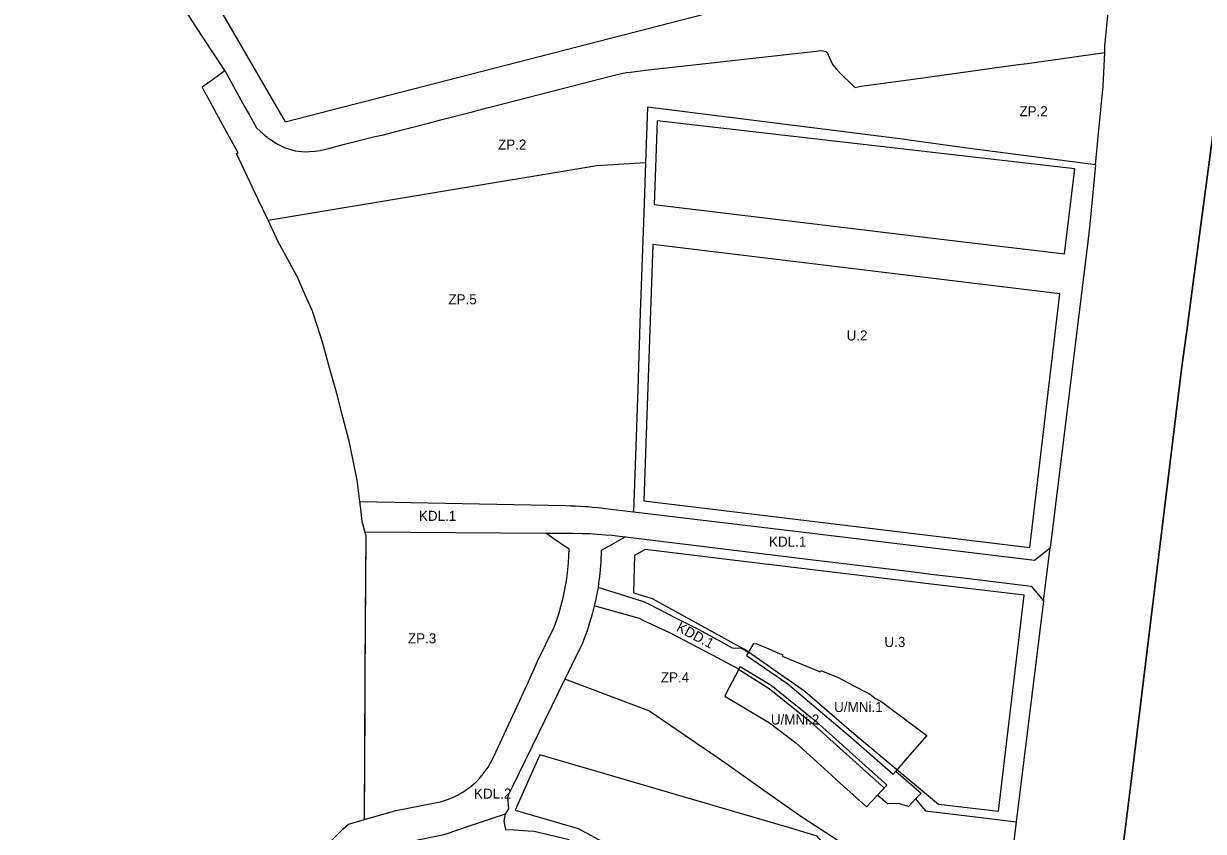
# Model space of a CAD drawing. Extents: x 7427578 to 7429232, y 5547102 to 5548448.
# Drawn here: x 7428072 to 7428660, y 5547522 to 5547924 of the extents above; entities that cross this region are included whole.
import ezdxf

# ---------------------------------------------------------------- set-up
doc = ezdxf.new("R2010")
doc.units = 0
for name, color, linetype in [('LIN_Granica Planu', 7, 'Continuous'), ('LIN_Linia Zabudowy Nieprzekraczalna', 7, 'Continuous'), ('LIN_Linie Rozgraniczajace', 7, 'Continuous'), ('TXT_Oznaczenia Przeznaczenia', 7, 'Continuous')]:
    doc.layers.add(name, color=color, linetype=linetype)

msp = doc.modelspace()

# ---------------------------------------------------------------- linework, layer by layer
at = {"layer": 'LIN_Granica Planu'}
for points in [[(7428228.98, 5547520.95), (7428231.59, 5547523.32), (7428234.21, 5547525.69), (7428242.1, 5547527.99), (7428242.5, 5547598.62), (7428242.91, 5547669.26), (7428241.96, 5547672.78), (7428241.02, 5547676.3), (7428240.42, 5547681.38), (7428239.81, 5547686.46), (7428239.15, 5547691.75), (7428238.48, 5547697.04), (7428236.46, 5547706.78), (7428234.44, 5547716.52), (7428231.38, 5547728.4), (7428228.32, 5547740.27), (7428224.76, 5547753.07), (7428221.2, 5547765.86), (7428218.73, 5547773.5), (7428216.25, 5547781.15), (7428212.48, 5547789.66), (7428208.71, 5547798.17), (7428203.95, 5547806.94), (7428199.18, 5547815.71), (7428194.13, 5547826.46), (7428189.08, 5547837.21), (7428183.79, 5547848.51), (7428178.49, 5547859.81), (7428178.83, 5547859.98), (7428179.17, 5547860.14), (7428171.64, 5547873.88), (7428164.11, 5547887.63), (7428162.68, 5547890.25), (7428161.25, 5547892.87), (7428166.91, 5547896.97), (7428172.56, 5547901.07), (7428161.38, 5547918.19), (7428150.21, 5547935.3)], [(7428665.68, 5547877.89), (7428654.7, 5547795.42), (7428651.83, 5547773.84), (7428648.96, 5547752.25), (7428639.46, 5547674.85), (7428629.96, 5547597.45), (7428623.59, 5547545.62), (7428617.23, 5547493.78)]]:
    msp.add_lwpolyline(points, dxfattribs=at)
at = {"layer": 'LIN_Linia Zabudowy Nieprzekraczalna'}
msp.add_line((7428381.21, 5547686.74), (7428573.36, 5547663.57), dxfattribs=at)
for points in [[(7428142.27, 5548072), (7428125.7, 5548050.16), (7428145.32, 5547974.26), (7428202.61, 5547875.54), (7428509.21, 5547954.46), (7428604.85, 5547945.18), (7428623.63, 5548139.34), (7428464.48, 5548154.75), (7428464.48, 5548154.75)], [(7428387.79, 5547876.03), (7428386.34, 5547834.42), (7428532.04, 5547816.82), (7428590.73, 5547809.73), (7428595.77, 5547852.08)], [(7428432.15, 5547612.46), (7428432.22, 5547612.4), (7428461.39, 5547591.9), (7428485.79, 5547570.81), (7428527.92, 5547535.6), (7428557.73, 5547532.13), (7428570.52, 5547639.72), (7428522.86, 5547645.41), (7428480.39, 5547650.58), (7428430.78, 5547656.57), (7428395.48, 5547660.82), (7428381.88, 5547662.54), (7428376.52, 5547659.54), (7428376.12, 5547640.92), (7428385.32, 5547638.06), (7428427.92, 5547614.77)], [(7428329.45, 5547560.25), (7428317.14, 5547532.66), (7428348.48, 5547523.48), (7428419.09, 5547485.39), (7428479.17, 5547406.37), (7428527.46, 5547399.74), (7428536, 5547434.01), (7428536, 5547434.01), (7428502.3, 5547478.77), (7428467.47, 5547519.82), (7428467.47, 5547519.82), (7428454.97, 5547523.48)]]:
    msp.add_lwpolyline(points, close=True, dxfattribs=at)
for points in [[(7428588.37, 5547789.87), (7428385.64, 5547814.36), (7428381.21, 5547686.74)], [(7428573.36, 5547663.57), (7428588.37, 5547789.87)], [(7428443.6, 5547593.1), (7428433.79, 5547599.32), (7428428.39, 5547602.75)], [(7428500.81, 5547543.72), (7428500.02, 5547544.55), (7428465.67, 5547575.32), (7428443.6, 5547593.1)]]:
    msp.add_lwpolyline(points, dxfattribs=at)
at = {"layer": 'LIN_Linie Rozgraniczajace'}
msp.add_line((7428580.21, 5547636.88), (7428583.49, 5547663.39), dxfattribs=at)
for points in [[(7428610.65, 5547910.02), (7428610.8, 5547913.24), (7428612.62, 5547931.79), (7428613.59, 5547941.57), (7428614.56, 5547951.51), (7428616.89, 5547975.32), (7428619.5, 5548002.1), (7428621.45, 5548022.13), (7428623.35, 5548041.5), (7428625.12, 5548059.63), (7428626.99, 5548078.82), (7428628.88, 5548098.19), (7428631.03, 5548120.27), (7428633.19, 5548142.37), (7428635.26, 5548163.57), (7428637.68, 5548188.34), (7428639.03, 5548202.16), (7428639.7, 5548209.08), (7428642.48, 5548237.53), (7428644.51, 5548258.34), (7428645.39, 5548267.36), (7428646.37, 5548277.45)], [(7428172.56, 5547901.07), (7428161.38, 5547918.19), (7428150.21, 5547935.3), (7428144.8, 5547942.14), (7428139.39, 5547948.98), (7428130.06, 5547960.77), (7428125.03, 5547967.12), (7428120.61, 5547972.54), (7428114.73, 5547977.58), (7428108.84, 5547982.62), (7428096.04, 5547993.58), (7428086.98, 5548002.36), (7428077.46, 5548010), (7428072.43, 5548014.03)], [(7428172.56, 5547901.07), (7428182.54, 5547882.87), (7428184.65, 5547879.13), (7428188.37, 5547872.52), (7428190.21, 5547870.82), (7428194.08, 5547867.6), (7428198.26, 5547864.8), (7428200.35, 5547863.73), (7428202.73, 5547862.52), (7428207.55, 5547861.13), (7428212.56, 5547860.65), (7428214.84, 5547860.75), (7428217.59, 5547860.86), (7428220.06, 5547861.17), (7428224.92, 5547862.43), (7428232.18, 5547864.31), (7428239.45, 5547866.19), (7428246.71, 5547868.07), (7428251.64, 5547869.06), (7428259.57, 5547871.12), (7428266.82, 5547873.01), (7428274.08, 5547874.9), (7428281.34, 5547876.78), (7428288.6, 5547878.67), (7428295.86, 5547880.56), (7428303.12, 5547882.45), (7428305.24, 5547883), (7428364.63, 5547898.26), (7428367.26, 5547898.87), (7428372.5, 5547900.09), (7428374.61, 5547900.33), (7428382.06, 5547901.17), (7428389.51, 5547902.01), (7428396.96, 5547902.85), (7428404.42, 5547903.7), (7428411.87, 5547904.54), (7428419.32, 5547905.38), (7428426.77, 5547906.22), (7428434.23, 5547907.07), (7428441.68, 5547907.91), (7428449.13, 5547908.75), (7428456.58, 5547909.59), (7428464.04, 5547910.44), (7428468.15, 5547910.9), (7428469.43, 5547910.98), (7428470.55, 5547910.94), (7428471.87, 5547910.51), (7428472.59, 5547909.76), (7428475.03, 5547904.36), (7428475.81, 5547903.24), (7428478.05, 5547900.54), (7428486.28, 5547892.58), (7428489.28, 5547893.24), (7428509.15, 5547895.97), (7428514.11, 5547896.65), (7428567.51, 5547904), (7428572.05, 5547904.62), (7428610.65, 5547910.02)], [(7428606.08, 5547854.17), (7428607.6, 5547869.74), (7428609.89, 5547893.2), (7428610.65, 5547910.02)], [(7428194.13, 5547826.46), (7428189.08, 5547837.21), (7428183.79, 5547848.51), (7428178.49, 5547859.81), (7428178.83, 5547859.98), (7428179.17, 5547860.14), (7428171.64, 5547873.88), (7428164.11, 5547887.63), (7428162.68, 5547890.25), (7428161.25, 5547892.87), (7428166.91, 5547896.97), (7428172.56, 5547901.07)], [(7428606.08, 5547854.17), (7428543.35, 5547862.23), (7428514.55, 5547866.27), (7428509.94, 5547866.95), (7428383.04, 5547882.83), (7428382.09, 5547855.29)], [(7428617.23, 5547493.78), (7428623.59, 5547545.62), (7428629.96, 5547597.45), (7428639.46, 5547674.85), (7428648.96, 5547752.25), (7428651.83, 5547773.84), (7428654.7, 5547795.42), (7428665.68, 5547877.89)], [(7428194.13, 5547826.46), (7428357.87, 5547853.75), (7428382.09, 5547855.29)], [(7428382.09, 5547855.29), (7428381.22, 5547829.81), (7428379.41, 5547780.47), (7428378.74, 5547758.97), (7428378.18, 5547742.3), (7428376.5, 5547695.04), (7428376.01, 5547681.32)], [(7428606.08, 5547854.17), (7428603.19, 5547824.54), (7428602.34, 5547815.75), (7428583.49, 5547663.39)], [(7428239.81, 5547686.46), (7428239.15, 5547691.75), (7428238.48, 5547697.04), (7428236.46, 5547706.78), (7428234.44, 5547716.52), (7428231.38, 5547728.4), (7428228.32, 5547740.27), (7428224.76, 5547753.07), (7428221.2, 5547765.86), (7428218.73, 5547773.5), (7428216.25, 5547781.15), (7428212.48, 5547789.66), (7428208.71, 5547798.17), (7428203.95, 5547806.94), (7428199.18, 5547815.71), (7428194.13, 5547826.46)], [(7428242.38, 5547671.25), (7428241.96, 5547672.78), (7428241.02, 5547676.3), (7428240.42, 5547681.38), (7428239.81, 5547686.46)], [(7428239.81, 5547686.46), (7428342.06, 5547684.41), (7428344.62, 5547684.34), (7428347.21, 5547684.24), (7428349.71, 5547684.11), (7428351.82, 5547683.97), (7428353.38, 5547683.86), (7428355.66, 5547683.67), (7428358.66, 5547683.38), (7428361.99, 5547683.01), (7428376.01, 5547681.32)], [(7428376.01, 5547681.32), (7428466.28, 5547670.43), (7428575.67, 5547657.24), (7428583.49, 5547663.39)], [(7428242.1, 5547527.99), (7428242.41, 5547583.14), (7428242.5, 5547598.62), (7428242.52, 5547601.94), (7428242.68, 5547628.62), (7428242.91, 5547669.26), (7428242.38, 5547671.25)], [(7428242.38, 5547671.25), (7428332.38, 5547670.71)], [(7428242.1, 5547527.99), (7428257.78, 5547532.56), (7428275.73, 5547536.01), (7428280.02, 5547536.91), (7428283.42, 5547537.96), (7428286.47, 5547539.18), (7428288.53, 5547540.18), (7428291.1, 5547541.65), (7428295.07, 5547544.46), (7428297.7, 5547546.77), (7428299.25, 5547548.33), (7428301.29, 5547550.71), (7428303.7, 5547554.07), (7428306.56, 5547559.37), (7428323.42, 5547595.94), (7428324.61, 5547598.6), (7428326.78, 5547603.44), (7428328.33, 5547606.89), (7428336.57, 5547623.85), (7428338.03, 5547628.04), (7428339.02, 5547630.9), (7428341.22, 5547639.2), (7428342.7, 5547646.98), (7428343.23, 5547650.97), (7428343.76, 5547655.94), (7428343.92, 5547659.23), (7428344.08, 5547662.64), (7428338.15, 5547666.73), (7428332.38, 5547670.71)], [(7428332.38, 5547670.71), (7428337.4, 5547670.68), (7428341.76, 5547670.65), (7428346.07, 5547670.63), (7428350.56, 5547670.55), (7428354.4, 5547670.41), (7428357.97, 5547670.21), (7428362.08, 5547669.89), (7428365.42, 5547669.58), (7428367.81, 5547669.32), (7428369.12, 5547669.16), (7428372.13, 5547668.8)], [(7428372.13, 5547668.8), (7428365.1, 5547664.86), (7428360.04, 5547662.04), (7428359.81, 5547656.5), (7428359.49, 5547652.39), (7428359.14, 5547648.92), (7428358.72, 5547645.88), (7428358.4, 5547643.56)], [(7428372.13, 5547668.8), (7428464.2, 5547657.59), (7428490.63, 5547654.37), (7428517.06, 5547651.15), (7428524.16, 5547650.29), (7428528.62, 5547649.75), (7428540.44, 5547648.34), (7428574.07, 5547644.32), (7428580.21, 5547636.88)], [(7428358.4, 5547643.56), (7428357.68, 5547639.53), (7428357.11, 5547636.91), (7428356.57, 5547634.44)], [(7428433.26, 5547611.15), (7428429.83, 5547613.27), (7428425.42, 5547613.42), (7428418.29, 5547617.35), (7428408.11, 5547622.88), (7428397.87, 5547628.04), (7428383.98, 5547635.06), (7428381.22, 5547636.46), (7428358.4, 5547643.56)], [(7428580.21, 5547636.88), (7428566.6, 5547526.89)], [(7428356.57, 5547634.44), (7428355.52, 5547630.32), (7428354.08, 5547625.44), (7428352.93, 5547621.98), (7428351.84, 5547618.99), (7428350.29, 5547615.06), (7428347.91, 5547610.21), (7428345.25, 5547604.75), (7428343.36, 5547600.9), (7428341.88, 5547597.87)], [(7428428.52, 5547602.99), (7428415.14, 5547609.99), (7428394.44, 5547620.83), (7428380.9, 5547627.21), (7428379.02, 5547628.1), (7428356.57, 5547634.44)], [(7428433.26, 5547611.15), (7428435.97, 5547615.69), (7428437.41, 5547615.49), (7428442.25, 5547613.47), (7428447.93, 5547611.1), (7428450.38, 5547610.08), (7428450.09, 5547609.39), (7428460.18, 5547605.19), (7428469.06, 5547601.62), (7428469.36, 5547602.3), (7428477.99, 5547598.84), (7428485.81, 5547594.67), (7428493.64, 5547590.55), (7428496.6, 5547588.28), (7428499.18, 5547587.03), (7428514.37, 5547575.63), (7428516.93, 5547573.71), (7428522.06, 5547569.95), (7428512.32, 5547558.7), (7428506.67, 5547552.18)], [(7428433.26, 5547611.15), (7428432.41, 5547609.77), (7428452.99, 5547595.63), (7428484.31, 5547569.02), (7428505.36, 5547550.67), (7428506.67, 5547552.18)], [(7428428.52, 5547602.99), (7428421.91, 5547590.25), (7428421.54, 5547589.54), (7428443.72, 5547576.16), (7428456.94, 5547566.24), (7428474.68, 5547550.16), (7428477.54, 5547547.41), (7428491.67, 5547534.75), (7428492.09, 5547534.37), (7428497.61, 5547540.19)], [(7428428.52, 5547602.99), (7428429.22, 5547604.31), (7428444.57, 5547594.89), (7428466.97, 5547576.84), (7428501.41, 5547545.99), (7428502.26, 5547545.1), (7428497.61, 5547540.19)], [(7428341.88, 5547597.87), (7428315.82, 5547544.47), (7428313.84, 5547540.42), (7428313.29, 5547539.06), (7428313.79, 5547533.3), (7428312.16, 5547530.77)], [(7428341.88, 5547597.87), (7428341.79, 5547597.91)], [(7428545.16, 5547429.45), (7428543.24, 5547432.02), (7428522.47, 5547458.21), (7428524.09, 5547467.7), (7428510.35, 5547473.76), (7428499.26, 5547487.9), (7428490.03, 5547509.61), (7428460.3, 5547528.82), (7428439.33, 5547543.71), (7428424.82, 5547554), (7428418.3, 5547558.63), (7428383.69, 5547582.11), (7428341.88, 5547597.87)], [(7428506.67, 5547552.18), (7428512.96, 5547546.7), (7428519.25, 5547541.22), (7428516.52, 5547538.34)], [(7428516.52, 5547538.34), (7428512.94, 5547534.56), (7428508.05, 5547536.04), (7428502.52, 5547535.91), (7428497.61, 5547540.19)], [(7428516.52, 5547538.34), (7428518.63, 5547535.71), (7428521.52, 5547532.36), (7428550.56, 5547528.84), (7428566.6, 5547526.89)], [(7428312.16, 5547530.77), (7428292.78, 5547524.27), (7428289.37, 5547523.1), (7428281.59, 5547520.42), (7428247.17, 5547513.22), (7428242.05, 5547511.49)], [(7428312.16, 5547530.77), (7428311.45, 5547527.22), (7428312.28, 5547523.08), (7428316.69, 5547522.84), (7428323.59, 5547522.46), (7428326.59, 5547522.29), (7428344.08, 5547518.11)], [(7428162.84, 5547465.04), (7428166.65, 5547468.39), (7428171.05, 5547472.06), (7428179.25, 5547479.07), (7428187.34, 5547484.04), (7428195.78, 5547489.77), (7428204.21, 5547495.5), (7428206.45, 5547497.26), (7428208.69, 5547499.03), (7428211.36, 5547501.59), (7428214.02, 5547504.16), (7428217.27, 5547507.84), (7428220.51, 5547511.53), (7428221.67, 5547512.96), (7428222.84, 5547514.39), (7428223.75, 5547515.49), (7428224.65, 5547516.59), (7428226.82, 5547518.77), (7428228.98, 5547520.95), (7428231.59, 5547523.32), (7428234.21, 5547525.69), (7428242.1, 5547527.99)], [(7428566.6, 5547526.89), (7428563.7, 5547503.51), (7428553.9, 5547464.36), (7428545.16, 5547429.45)]]:
    msp.add_lwpolyline(points, dxfattribs=at)

# ---------------------------------------------------------------- texts
at = {"layer": 'TXT_Oznaczenia Przeznaczenia'}
for s, p in [('ZP.2', (7428568.2, 5547878.29)), ('ZP.2', (7428308.62, 5547861.68)), ('ZP.5', (7428283.92, 5547784.61)), ('U.2', (7428482.15, 5547766.63)), ('KDL.1', (7428269.23, 5547676.78)), ('KDL.1', (7428443.55, 5547663.93)), ('ZP.3', (7428263.77, 5547615.76)), ('U.3', (7428501.01, 5547613.98)), ('ZP.4', (7428389.67, 5547596.32)), ('U/MNi.1', (7428475.97, 5547581.57)), ('U/MNi.2', (7428444.46, 5547575.34)), ('KDL.2', (7428296.65, 5547538.45))]:
    msp.add_text(s, height=5, dxfattribs=at).set_placement(p)
msp.add_text('KDD.1', height=5, rotation=332.35151, dxfattribs=at).set_placement((7428397, 5547622.16))

doc.saveas('drawing.dxf')
